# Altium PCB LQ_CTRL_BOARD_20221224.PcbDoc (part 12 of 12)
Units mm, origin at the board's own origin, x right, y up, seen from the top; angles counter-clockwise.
Board outline 260 x 142 mm, 6 copper layers (Top Layer, Mid-Layer 1, Mid-Layer 2, Mid-Layer 3, Mid-Layer 4, Bottom Layer); 1105 components, 1039 nets, 3898 pads, 1277 vias.
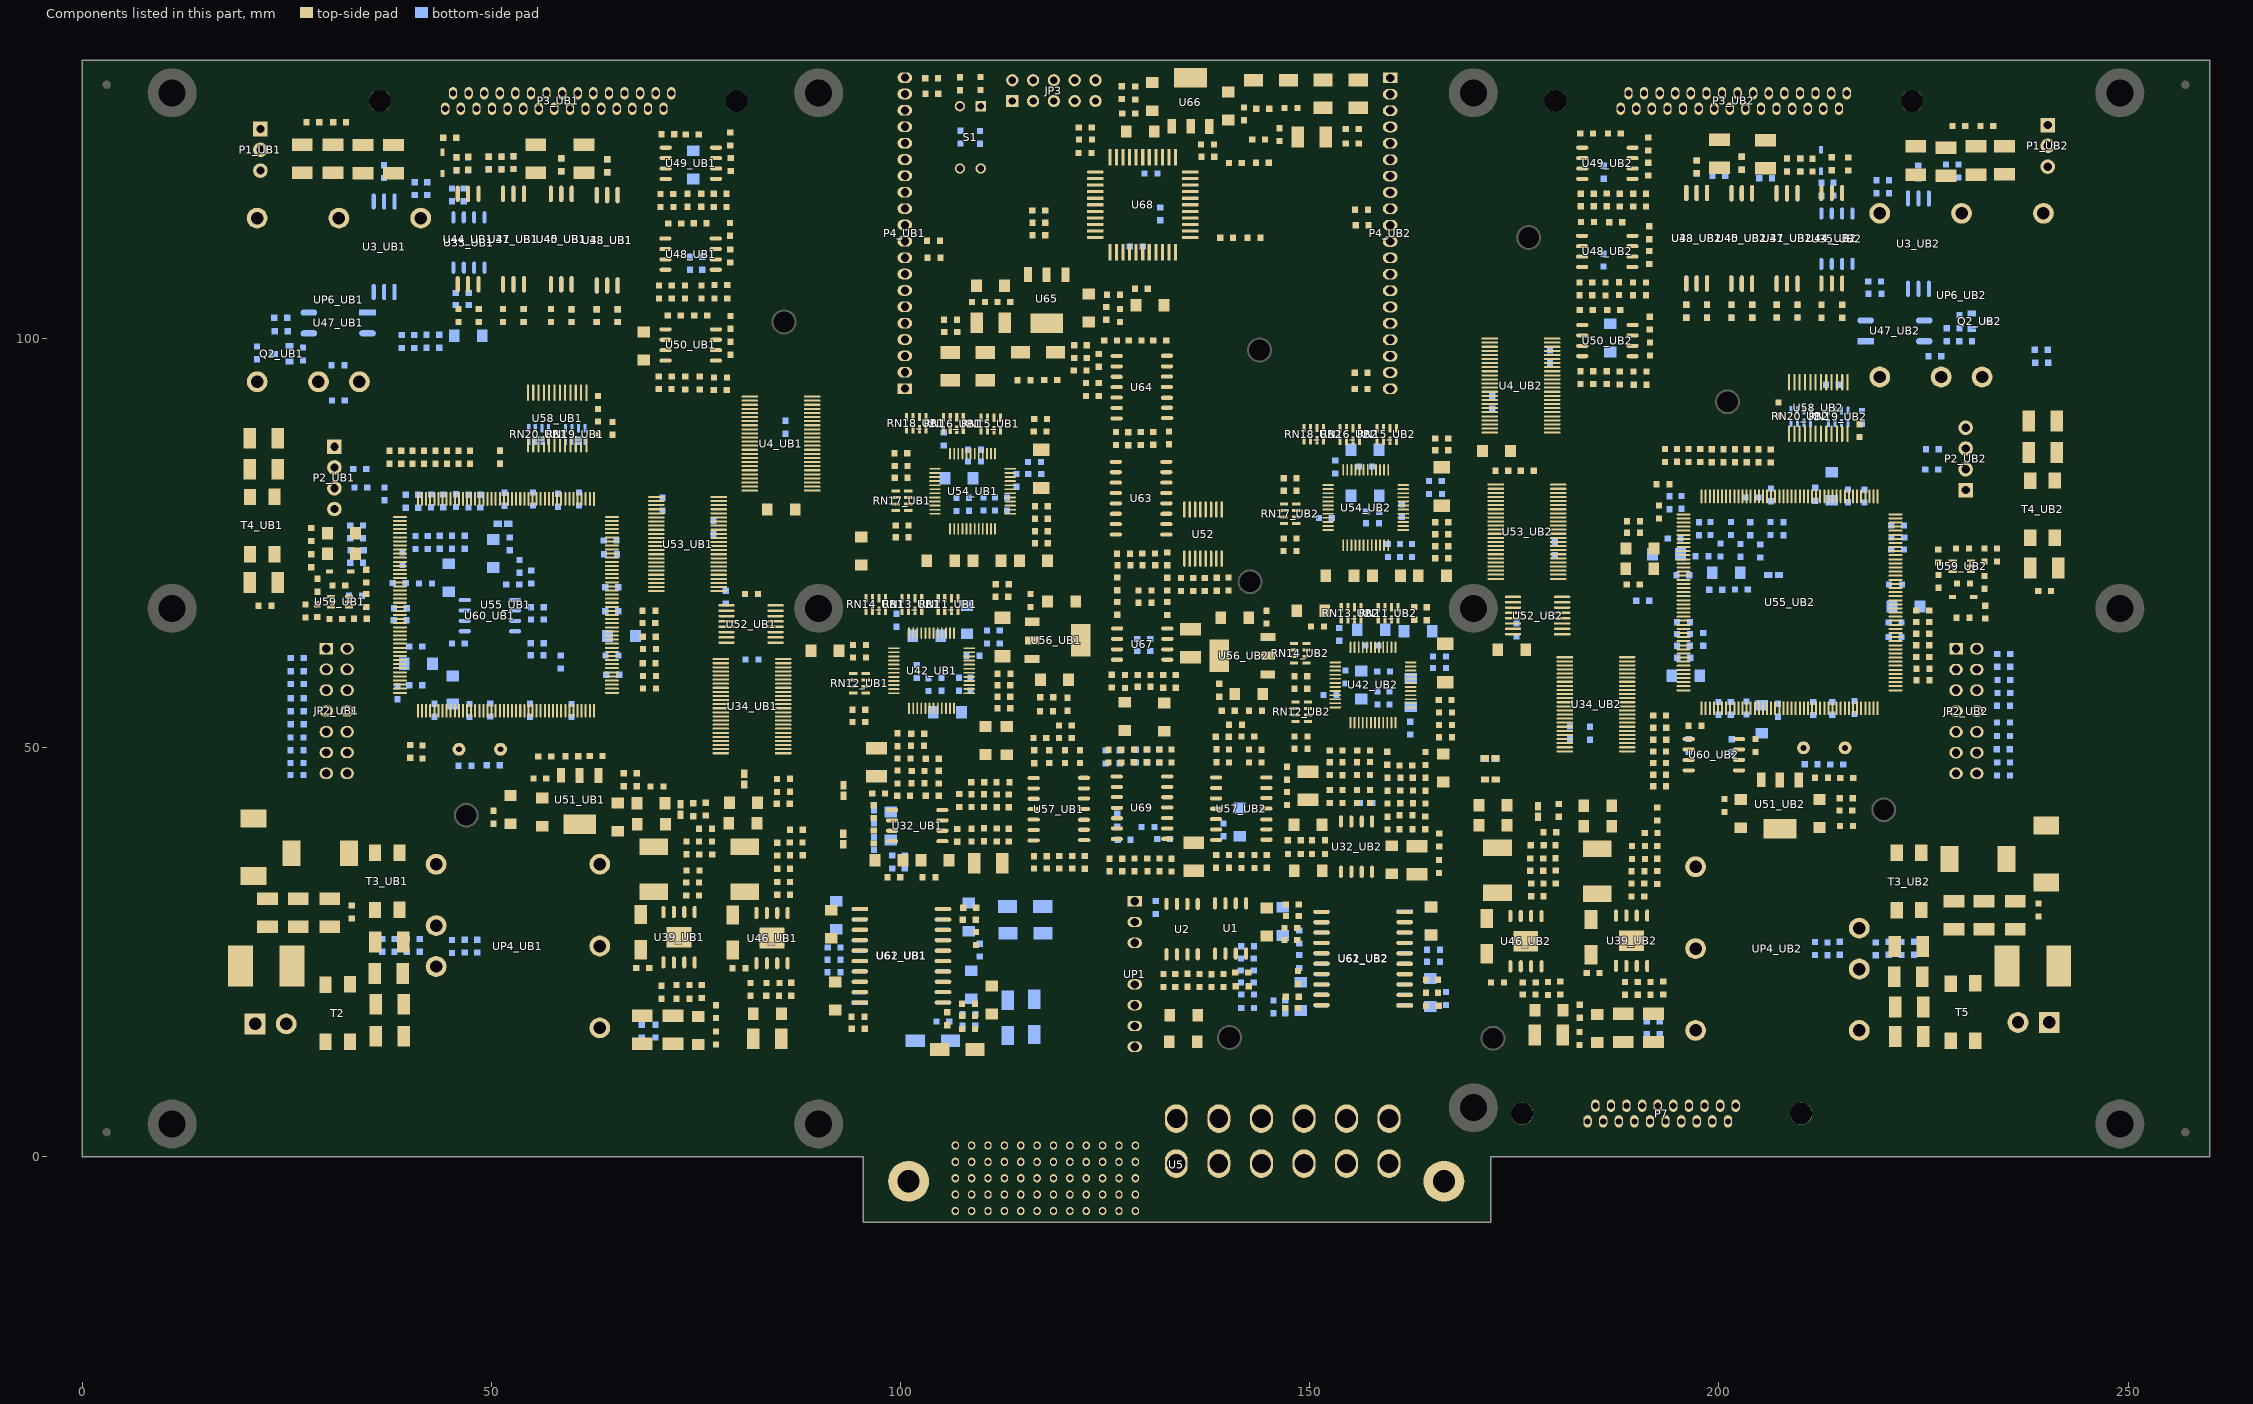
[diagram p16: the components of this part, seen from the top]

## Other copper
Top Layer:
  rectangle net HVCC: 35.535,0.686 84.988,10.262
  rectangle net HVCC: 214.046,0.483 227.076,9.093
  rectangle net GND_UB2: 186.741,24.655 191.846,27.991
  rectangle net GND_UB2: 173.787,24.689 179.019,27.991
  rectangle net GND_UB1: 81.712,25.07 87.122,28.143
  rectangle net GND_UB1: 70.002,25.133 75.364,28.194
  rectangle net GND_UB2: 207.137,68.834 209.908,72.492
  rectangle net GND_UB2: 172.187,44.831 175.971,47.041
  rectangle net AGND_UB2: 167.996,44.78 171.958,47.371
  rectangle net +5V_UB2: 172.237,47.676 175.946,49.886
  rectangle net +5VA_UB2: 168.173,47.727 171.958,49.86
  rectangle net +3.3V_UB2: 175.362,39.04 179.197,42.062
  rectangle net +3.3V_UB2: 170,35.941 177.317,38.913
  rectangle net +3.3V_UB2: 172.949,35.941 177.317,42.062
  rectangle net +3.3V_UB2: 172.517,36.144 176.251,44.018
  rectangle net NetC290_UB2_1: 169.875,28.6 174.854,33.401
  rectangle net +5V_UB2: 186.69,39.027 191.364,41.656
  rectangle net +5V_UB2: 185.522,37.124 189.586,43.764
  rectangle net +5V_UB2: 183.286,36.043 189.687,38.684
  rectangle net NetC252_UB2_1: 183.261,28.677 187.782,33.198
  rectangle net 28VA_UB1: 39.248,13.64 44.552,24.536
  region net NetC252_UB1_1: 71.374,28.981 71.374,33.401 67.437,33.401 67.437,28.981
  region net +5V_UB1: 75.438,39.497 75.438,41.377 70.536,41.377 70.536,39.497
  region net +5V_UB1: 71.933,36.297 71.933,43.993 69.444,43.993 69.444,36.297
  region net NetC290_UB1_1: 82.779,28.829 82.779,33.401 78.715,33.401 78.715,28.829
  region net GND_UB1: 74.447,25.527 74.447,27.534 67.488,27.534 67.488,25.527
  region net GND_UB1: 85.801,25.324 85.801,27.407 78.74,27.407 78.74,25.324
  region net GND_UB1: 88.417,13.132 88.417,18.39 84.658,18.39 84.658,13.132
  region net +3.3V_UB1: 86.919,39.599 86.919,42.24 80.874,42.24 80.874,39.599
  region net +3.3V_UB1: 83.566,36.424 83.566,45.949 80.569,45.949 80.569,36.424
  region net GND_UB1: 79.604,39.954 79.604,44.602 78.054,44.602 78.054,39.954
  region net GND_UB1: 78.943,41.275 78.943,45.745 77.374,45.745 77.374,41.275
  region net AGND_UB1: 94.402,36.627 94.402,38.71 91.633,38.71 91.633,36.627
  region net GND_UB1: 94.351,38.938 94.351,41.072 91.684,41.072 91.684,38.938
  rectangle net +3.3V_UB1: 81.991,41.631 85.166,44.856
  rectangle net AGNDMS: 151.181,121.31 154.788,126.086
  rectangle net +5VA_UB1: 91.542,44.933 94.59,47.346
  rectangle net +5V_UB1: 91.516,42.596 94.564,44.526
  rectangle net GND_UB1: 90.094,38.964 94.361,41.808
  pour cut-out: 187.528,31.166 187.604,31.242 187.604,37.821 183.244,37.821 183.187,37.764 183.286,37.665 183.286,30.709 187.503,30.709 187.554,30.759 187.554,32.944
  pour cut-out: 174.65,31.699 174.727,31.775 174.727,38.354 170.367,38.354 170.31,38.297 170.409,38.198 170.409,31.242 174.625,31.242 174.676,31.293 174.676,33.477
  pour cut-out: 82.906,31.826 82.982,31.902 82.982,38.481 78.622,38.481 78.565,38.424 78.664,38.325 78.664,31.369 82.88,31.369 82.931,31.42 82.931,33.604
  pour cut-out: 71.679,32.08 71.755,32.156 71.755,38.735 67.395,38.735 67.338,38.678 67.437,38.579 67.437,31.623 72.873,31.115 71.704,31.674 71.704,33.858
Mid-Layer 1:
  rectangle net HVC1: 142.748,4.663 145.517,12.04
  rectangle net HVC1: 143.231,9.5 155.88,12.04
  rectangle net GND_UB2: 195.529,13.917 198.831,17.697
  rectangle net GND_UB2: 170.79,24.003 191.897,28.55
  rectangle net 28VGND1: 23.241,13.513 27.915,18.974
  rectangle net 28VGND1: 30.759,21.844 34.722,27.813
  rectangle net 28VGND1: 28.397,31.344 32.817,39.522
  rectangle net GND_UB2: 173.457,44.171 177.089,47.015
  rectangle net AGND_UB2: 165.887,44.78 170.459,47.32
  rectangle net AGND_UB2: 163.652,44.78 167.716,49.407
  rectangle net GND_UB1: 67.437,23.8 86.36,29.591
  rectangle net GND_UB1: 90.399,38.964 94.361,41.783
  rectangle net GND_UB1: 61.163,33.325 65.761,37.998
  rectangle net ISO_GND_UB1: 18.999,113.411 23.774,117.272
  rectangle net AGND_UB1: 91.592,36.119 96.368,38.557
  rectangle net ISO_GND_UB2: 217.932,113.843 221.59,117.272
  rectangle net ISO_GND_UB2: 218.313,123.012 223.114,125.4
  rectangle net 28VGND2: 230.276,39.497 237.084,42.469
  rectangle net 28VGND2: 236.677,25.933 241.224,30.378
  rectangle net 28VGND2: 233.426,13.792 238.125,19.152
  rectangle net HVC1: 143.662,7.264 161.468,11.963
Mid-Layer 2:
  rectangle net GND_UB2: 170.739,23.901 192.481,28.931
  rectangle net GND_UB1: 78.892,23.571 86.309,29.997
  rectangle net GND_UB1: 66.98,24.301 75.252,29.642
  rectangle net GND_UB1: 91.618,38.964 94.336,41.783
  rectangle net ISO_+15V_UB2: 236.728,113.826 241.732,117.856
  rectangle net HVB1: 137.643,7.391 161.341,12.065
Mid-Layer 3:
  rectangle net +5V_UB2: 173.101,47.269 176.174,50.524
  rectangle net +5VA_UB2: 167.945,47.396 170.028,50.394
  rectangle net GND_UB1: 59.792,29.489 65.43,37.795
  rectangle net AGND_UB1: 87.655,34.239 95.758,38.633
Mid-Layer 4:
  rectangle net HVA1: 134.722,7.417 161.417,11.989
  rectangle net +3.3VD_UB2: 205.232,47.092 207.67,50.216
Bottom Layer:
  rectangle net HVGND: 31.318,0.711 84.988,10.287
  rectangle net HVGND: 213.995,0.584 232.639,9.093
  rectangle net GND_UB2: 195.936,13.691 198.857,17.628
  rectangle net GND_UB2: 170.688,24.308 192.763,28.346
  rectangle net 28VGND1: 23.19,13.868 28.372,19.025
  rectangle net 28VGND1: 30.886,21.641 34.671,27.457
  rectangle net 28VGND1: 28.885,34.214 32.334,39.294
  rectangle net +5V_UB2: 172.263,47.701 175.92,49.886
  rectangle net +5VA_UB2: 168.199,47.701 171.933,49.798
  rectangle net AGND_UB2: 204.038,70.18 205.918,72.187
  rectangle net AGND_UB2: 164.414,44.806 170.383,47.396
  rectangle net GND_UB1: 82.118,25.679 85.192,28.88
  rectangle net GND_UB1: 67.488,24.867 81.813,29.845
  region net +28VB_UB1: 35.382,92.024 35.382,97.155 31.775,97.155 31.775,92.024
  region net 28VGNDB_UB1: 30.81,92.151 30.81,97.104 24.74,97.104 24.74,92.151
  rectangle net ISO_GND_UB2: 218.313,113.944 223.495,118.237
  rectangle net 28VA_UB2: 210.617,25.629 224.434,29.185
  rectangle net 28GND_UB2: 210.642,21.539 224.511,25.197
  rectangle net GND_UB1: 90.094,38.964 94.361,41.808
